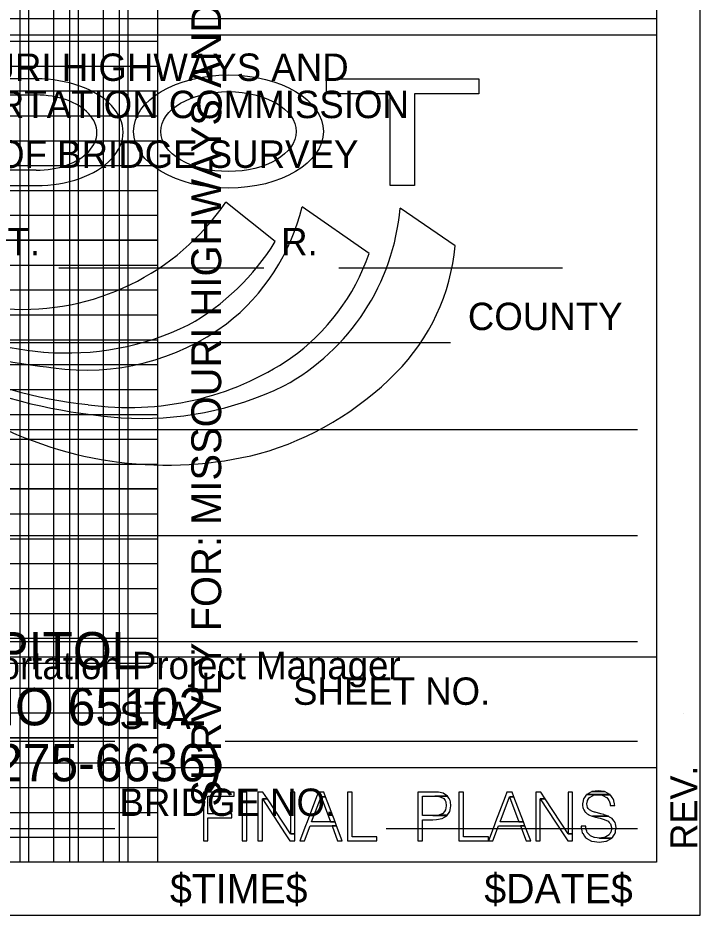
# Model space of a CAD drawing. Extents: x -0.2 to 31.4, y -0.2 to 20.6.
# Drawn here: x 28.681 to 31.425, y -0.212 to 3.393 of the extents above; entities that cross this region are included whole.
import ezdxf

# ---------------------------------------------------------------- set-up
doc = ezdxf.new("R2010")
doc.units = 0
for name, color, linetype in [('Border-Border', 7, 'Continuous'), ('Border-Bridge survey title block', 7, 'Continuous'), ('Border-Construction Final Plans Stamp', 7, 'Continuous'), ('Border-Cookie Cutter Template', 7, 'Continuous'), ('Border-Date stamp', 7, 'Continuous'), ('Border-English xsection major lines', 7, 'Continuous'), ('Border-English xsection minor lines', 7, 'Continuous'), ('Border-Full profile major grid lines', 7, 'Continuous'), ('Border-Geopak xsection major grid lines', 7, 'Continuous'), ('Border-Geopak xsection minor lines 1', 7, 'Continuous'), ('Border-Geopak xsection minor lines 2', 7, 'Continuous'), ('Border-Plan-profile major grid lines', 7, 'Continuous'), ('Border-Plotting block', 7, 'Continuous'), ('Border-Revision note', 7, 'Continuous'), ('Border-Time stamp', 7, 'Continuous'), ('Border-Title block - A-size Landscape Electronic Seal', 7, 'Continuous'), ('Border-Title block - Final Plans Consultant Manual Seal', 7, 'Continuous'), ('Border-Title block - Final Plans Electronic Seal', 7, 'Continuous'), ('Border-Title block - Location Survey Electronic Seal', 7, 'Continuous'), ('Border-Title block - Standard Plans Electronic Seal', 7, 'Continuous'), ('Border-Xsection shape', 7, 'Continuous')]:
    doc.layers.add(name, color=color, linetype=linetype)

msp = doc.modelspace()

# ---------------------------------------------------------------- linework, layer by layer
at = {"layer": 'Border-Border'}
for p, q in [((31.25, 20.375), (31.25, 0)), ((31.25, 0), (0, 0)), ((31.4249, -0.2125), (31.4249, -0.2125))]:
    msp.add_line(p, q, dxfattribs=at)
at = {"layer": 'Border-Bridge survey title block'}
for p, q in [((26.7664, 3.3906), (31.2499, 3.3906)), ((28.845, 2.389), (29.6704, 2.389)), ((29.9715, 2.389), (30.872, 2.389)), ((28.2689, 2.0882), (30.4216, 2.0882)), ((28.5253, 1.7386), (31.1728, 1.7386)), ((28.2056, 1.3126), (31.1728, 1.3126)), ((28.0914, 0.8866), (31.1728, 0.8866)), ((27.9544, 0.4866), (29.0704, 0.4866)), ((29.5148, 0.4866), (31.1728, 0.4866)), ((27.7414, 0.1354), (29.0704, 0.1354)), ((30.1618, 0.1354), (31.1728, 0.1354))]:
    msp.add_line(p, q, dxfattribs=at)
at = {"layer": 'Border-Construction Final Plans Stamp'}
msp.add_line((29.2421, 0.38), (31.2499, 0.38), dxfattribs=at)
for points in [[(29.4267, 0.1788), (29.4267, 0.0858), (29.4449, 0.0858), (29.4449, 0.1788), (29.541, 0.1788), (29.541, 0.1949), (29.4449, 0.1949), (29.4449, 0.2658), (29.5508, 0.2658), (29.5508, 0.2818), (29.4267, 0.2818), (29.4267, 0.2658), (29.4267, 0.1949)], [(29.583, 0.2818), (29.583, 0.0858), (29.6015, 0.0858), (29.6015, 0.2818)], [(29.6465, 0.1137), (29.6465, 0.0858), (29.6642, 0.0858), (29.6642, 0.1137), (29.6642, 0.254), (29.6846, 0.254), (29.6664, 0.2818), (29.6465, 0.2818), (29.6465, 0.254)], [(29.7564, 0.1137), (29.7748, 0.0858), (29.7947, 0.0858), (29.7947, 0.1137), (29.777, 0.1137), (29.6847, 0.254), (29.6642, 0.254)], [(29.777, 0.2818), (29.777, 0.1137), (29.7947, 0.1137), (29.7947, 0.2818)], [(29.8382, 0.1462), (29.8153, 0.0858), (29.834, 0.0858), (29.8565, 0.1462), (29.9627, 0.1462), (29.9567, 0.1619), (29.8623, 0.1619), (29.9004, 0.2629), (29.9183, 0.2629), (29.9112, 0.2818), (29.8897, 0.2818), (29.8825, 0.2629), (29.8442, 0.1619)], [(29.9004, 0.2629), (29.9385, 0.1619), (29.9567, 0.1619), (29.9184, 0.2629)], [(30.0063, 0.1018), (30.0063, 0.0858), (30.125, 0.0858), (30.125, 0.1018), (30.0248, 0.1018), (30.0248, 0.2818), (30.0063, 0.2818)], [(30.2897, 0.1709), (30.2897, 0.0858), (30.3078, 0.0858), (30.3078, 0.1709), (30.3495, 0.1709), (30.3641, 0.1714), (30.3869, 0.1754), (30.4062, 0.1862), (30.407, 0.1873), (30.3078, 0.1873), (30.3078, 0.1874), (30.3078, 0.189), (30.3078, 0.1961), (30.3078, 0.2043), (30.3078, 0.2103), (30.3078, 0.2269), (30.3078, 0.2271), (30.3078, 0.2432), (30.3078, 0.2473), (30.3078, 0.2557), (30.3078, 0.2632), (30.3078, 0.2649), (30.3078, 0.2654), (30.3078, 0.2658), (30.4084, 0.2658), (30.3921, 0.2768), (30.3724, 0.2812), (30.3583, 0.2818), (30.2897, 0.2818), (30.2897, 0.2812), (30.2897, 0.2768), (30.2897, 0.2658), (30.2897, 0.2654), (30.2897, 0.2649), (30.2897, 0.2632), (30.2897, 0.2557), (30.2897, 0.2473), (30.2897, 0.2432), (30.2897, 0.2271), (30.2897, 0.2269), (30.2897, 0.2103), (30.2897, 0.2043), (30.2897, 0.1961), (30.2897, 0.189), (30.2897, 0.1874), (30.2897, 0.1873), (30.2897, 0.1862), (30.2897, 0.1754), (30.2897, 0.1714)], [(30.3574, 0.2658), (30.3644, 0.2654), (30.4089, 0.2654), (30.4084, 0.2658)], [(30.3907, 0.1961), (30.3747, 0.189), (30.4081, 0.189), (30.413, 0.1961), (30.4186, 0.2043), (30.4197, 0.2103), (30.4196, 0.2103), (30.4226, 0.2269), (30.4226, 0.2271), (30.4204, 0.2432), (30.4199, 0.2473), (30.415, 0.2557), (30.4106, 0.2632), (30.4096, 0.2649), (30.4089, 0.2654), (30.3644, 0.2654), (30.3678, 0.2649), (30.3794, 0.2632), (30.3936, 0.2557), (30.3991, 0.2473), (30.4017, 0.2432), (30.4041, 0.2271), (30.4041, 0.2269), (30.4012, 0.2103), (30.3968, 0.2043)], [(30.4545, 0.1018), (30.4545, 0.0858), (30.5732, 0.0858), (30.5732, 0.1018), (30.473, 0.1018), (30.473, 0.2818), (30.4545, 0.2818)], [(30.5961, 0.1462), (30.5732, 0.0858), (30.5919, 0.0858), (30.6144, 0.1462), (30.7206, 0.1462), (30.7146, 0.1619), (30.6202, 0.1619), (30.6583, 0.2629), (30.6762, 0.2629), (30.6691, 0.2818), (30.6476, 0.2818), (30.6404, 0.2629), (30.6021, 0.1619)], [(30.6583, 0.2629), (30.6964, 0.1619), (30.7146, 0.1619), (30.6763, 0.2629)], [(30.7642, 0.1137), (30.7642, 0.0858), (30.7819, 0.0858), (30.7819, 0.1137), (30.7819, 0.254), (30.8024, 0.254), (30.7841, 0.2818), (30.7642, 0.2818), (30.7642, 0.254)], [(30.8742, 0.1137), (30.8925, 0.0858), (30.9124, 0.0858), (30.9124, 0.1137), (30.8947, 0.1137), (30.8024, 0.254), (30.7819, 0.254)], [(30.8947, 0.2818), (30.8947, 0.1137), (30.9124, 0.1137), (30.9124, 0.2818)], [(30.9904, 0.1853), (30.9927, 0.1844), (31.0561, 0.1844), (31.0546, 0.1853), (31.0395, 0.1906), (31.0394, 0.1906), (31.0378, 0.1912), (31.0257, 0.1946), (31.0029, 0.2004), (31.0002, 0.2012), (30.9921, 0.2036), (30.9798, 0.2103), (30.9753, 0.2161), (30.9721, 0.2203), (30.9707, 0.2272), (30.9695, 0.2337), (30.9695, 0.2339), (30.9695, 0.2344), (30.9696, 0.2349), (30.9717, 0.2471), (30.9719, 0.2486), (30.976, 0.2543), (30.9765, 0.2549), (30.9765, 0.2549), (30.9801, 0.2599), (30.9805, 0.2605), (30.9953, 0.2685), (30.9959, 0.2689), (31.0147, 0.2711), (31.0635, 0.2711), (31.0628, 0.2721), (30.9684, 0.2721), (30.9677, 0.2711), (30.966, 0.2689), (30.9658, 0.2685), (30.96, 0.2605), (30.9596, 0.2599), (30.9559, 0.2549), (30.9555, 0.2543), (30.9544, 0.2486), (30.9541, 0.2471), (30.9517, 0.2349), (30.9516, 0.2344), (30.9517, 0.2339), (30.9517, 0.2337), (30.9526, 0.2272), (30.9536, 0.2203), (30.9542, 0.2161), (30.9575, 0.2103), (30.9615, 0.2036), (30.9629, 0.2012), (30.964, 0.2004), (30.9714, 0.1946), (30.9758, 0.1912), (30.9765, 0.1906)], [(30.9693, 0.2726), (30.9684, 0.2721), (31.0628, 0.2721), (31.0624, 0.2726), (31.0425, 0.2832), (31.0399, 0.2836), (30.9893, 0.2836), (30.9886, 0.2832)], [(31.0156, 0.2872), (30.9893, 0.2836), (31.0399, 0.2836)], [(31.063, 0.2337), (31.0634, 0.2272), (31.0815, 0.2272), (31.0811, 0.2337), (31.0811, 0.2339), (31.0811, 0.2344), (31.0811, 0.2349), (31.0778, 0.2471), (31.0778, 0.2471), (31.0774, 0.2486), (31.0759, 0.2543), (31.0757, 0.2549), (31.0719, 0.2599), (31.0715, 0.2605), (31.0654, 0.2685), (31.0652, 0.2689), (31.0652, 0.2689), (31.0635, 0.2711), (31.0147, 0.2711), (31.0313, 0.2689), (31.0336, 0.2685), (31.0489, 0.2605), (31.05, 0.2599), (31.0537, 0.2549), (31.0541, 0.2543), (31.0582, 0.2486), (31.0593, 0.2471), (31.0627, 0.2349), (31.0628, 0.2344), (31.0629, 0.2339)], [(30.3573, 0.1874), (30.3498, 0.1873), (30.407, 0.1873), (30.407, 0.1874)], [(30.3746, 0.189), (30.3574, 0.1874), (30.407, 0.1874), (30.4081, 0.189)], [(31.0224, 0.0968), (31.02, 0.0965), (31.0694, 0.0965), (31.0699, 0.0968), (31.0712, 0.0976), (31.0721, 0.0988), (31.0725, 0.0994), (31.0771, 0.1061), (31.0795, 0.1096), (31.0835, 0.1154), (31.0839, 0.1183), (31.0839, 0.1183), (31.0841, 0.1197), (31.0848, 0.1245), (31.0863, 0.1343), (31.0868, 0.1377), (31.0871, 0.1392), (31.0842, 0.1536), (31.0829, 0.1598), (31.0791, 0.1646), (31.0734, 0.1721), (31.0708, 0.1754), (31.0689, 0.1766), (31.0689, 0.1766), (31.0611, 0.1813), (31.0561, 0.1844), (30.9927, 0.1844), (31.0046, 0.1813), (31.0232, 0.1766), (31.0272, 0.1754), (31.0392, 0.1721), (31.0552, 0.1646), (31.0596, 0.1598), (31.0652, 0.1536), (31.0688, 0.1392), (31.0687, 0.1377), (31.0684, 0.1343), (31.0677, 0.1245), (31.0649, 0.1197), (31.0641, 0.1183), (31.0624, 0.1154), (31.0591, 0.1096), (31.0531, 0.1061), (31.0416, 0.0994), (31.0374, 0.0988), (31.028, 0.0976)], [(29.9444, 0.1462), (29.9668, 0.0858), (29.9856, 0.0858), (29.9627, 0.1462)], [(30.7022, 0.1462), (30.7247, 0.0858), (30.7435, 0.0858), (30.7206, 0.1462)], [(30.9897, 0.0843), (31.0197, 0.0805), (31.0452, 0.0843), (31.049, 0.0849), (31.0694, 0.0965), (31.02, 0.0965), (31.0174, 0.0968), (31.011, 0.0976), (31.0003, 0.0988), (30.999, 0.0994), (30.9835, 0.1061), (30.9803, 0.1096), (30.9748, 0.1154), (30.9748, 0.1154), (30.9721, 0.1183), (30.9709, 0.1197), (30.9692, 0.1245), (30.9658, 0.1343), (30.9654, 0.1377), (30.9653, 0.1392), (30.9648, 0.1452), (30.9468, 0.1452), (30.9469, 0.1392), (30.947, 0.1377), (30.9477, 0.1343), (30.9496, 0.1245), (30.9505, 0.1197), (30.9508, 0.1183), (30.9528, 0.1154), (30.9569, 0.1096), (30.9593, 0.1061), (30.964, 0.0994), (30.9645, 0.0988), (30.9653, 0.0976), (30.9659, 0.0968), (30.9665, 0.0965), (30.9886, 0.0849)]]:
    msp.add_lwpolyline(points, close=True, dxfattribs=at)
at = {"layer": 'Border-Cookie Cutter Template'}
for p, q in [((29.2421, 20.375), (29.2421, 0)), ((31.2499, 20.375), (31.2499, 0)), ((31.2499, 0), (0, 0))]:
    msp.add_line(p, q, dxfattribs=at)
at = {"layer": 'Border-English xsection major lines'}
for p, q in [((0, 3), (29.2421, 3)), ((0, 2), (29.2421, 2)), ((0, 1), (29.2421, 1))]:
    msp.add_line(p, q, dxfattribs=at)
at = {"layer": 'Border-English xsection minor lines'}
for p, q in [((28.6899, 0), (28.6899, 20.375)), ((28.8899, 0), (28.8899, 20.375)), ((29.0899, 0), (29.0899, 20.375)), ((0, 3.2), (29.2421, 3.2)), ((0, 2.8), (29.2421, 2.8)), ((0, 2.6), (29.2421, 2.6)), ((0, 2.4), (29.2421, 2.4)), ((0, 2.2), (29.2421, 2.2)), ((0, 1.8), (29.2421, 1.8)), ((0, 1.6), (29.2421, 1.6)), ((0, 1.4), (29.2421, 1.4)), ((0, 1.2), (29.2421, 1.2)), ((0, 0.8), (29.2421, 0.8)), ((0, 0.6), (29.2421, 0.6)), ((0, 0.4), (29.2421, 0.4)), ((0, 0.2), (29.2421, 0.2))]:
    msp.add_line(p, q, dxfattribs=at)
at = {"layer": 'Border-Full profile major grid lines'}
for p, q in [((29.2421, 2.5), (0, 2.5)), ((29.2421, 1.5), (0, 1.5)), ((29.2421, 0.5), (0, 0.5))]:
    msp.add_line(p, q, dxfattribs=at)
at = {"layer": 'Border-Geopak xsection major grid lines'}
for p, q in [((0, 3), (29.2421, 3)), ((0, 2), (29.2421, 2)), ((0, 1), (29.2421, 1))]:
    msp.add_line(p, q, dxfattribs=at)
at = {"layer": 'Border-Geopak xsection minor lines 1'}
for p, q in [((28.7249, 0), (28.7249, 20.375)), ((28.9249, 0), (28.9249, 20.375)), ((29.1249, 0), (29.1249, 20.375)), ((0, 3.3), (29.2421, 3.3)), ((0, 3.1), (29.2421, 3.1)), ((0, 2.9), (29.2421, 2.9)), ((0, 2.7), (29.2421, 2.7)), ((0, 2.5), (29.2421, 2.5)), ((0, 2.3), (29.2421, 2.3)), ((0, 2.1), (29.2421, 2.1)), ((0, 1.9), (29.2421, 1.9)), ((0, 1.7), (29.2421, 1.7)), ((0, 1.5), (29.2421, 1.5)), ((0, 1.3), (29.2421, 1.3)), ((0, 1.1), (29.2421, 1.1)), ((0, 0.9), (29.2421, 0.9)), ((0, 0.7), (29.2421, 0.7)), ((0, 0.5), (29.2421, 0.5)), ((0, 0.3), (29.2421, 0.3)), ((0, 0.1), (29.2421, 0.1))]:
    msp.add_line(p, q, dxfattribs=at)
at = {"layer": 'Border-Geopak xsection minor lines 2'}
for p, q in [((28.8249, 0), (28.8249, 20.375)), ((29.0249, 0), (29.0249, 20.375)), ((0, 3.2), (29.2421, 3.2)), ((0, 2.8), (29.2421, 2.8)), ((0, 2.6), (29.2421, 2.6)), ((0, 2.4), (29.2421, 2.4)), ((0, 2.2), (29.2421, 2.2)), ((0, 1.8), (29.2421, 1.8)), ((0, 1.6), (29.2421, 1.6)), ((0, 1.4), (29.2421, 1.4)), ((0, 1.2), (29.2421, 1.2)), ((0, 0.8), (29.2421, 0.8)), ((0, 0.6), (29.2421, 0.6)), ((0, 0.4), (29.2421, 0.4)), ((0, 0.2), (29.2421, 0.2))]:
    msp.add_line(p, q, dxfattribs=at)
at = {"layer": 'Border-Plan-profile major grid lines'}
for p, q in [((29.2421, 2.5), (0, 2.5)), ((29.2421, 1.5), (0, 1.5)), ((29.2421, 0.5), (0, 0.5))]:
    msp.add_line(p, q, dxfattribs=at)
at = {"layer": 'Border-Plotting block'}
msp.add_lwpolyline([(-0.175, -0.2125), (31.4249, -0.2125), (31.4249, 20.5875), (-0.175, 20.5875)], close=True, dxfattribs=at)
at = {"layer": 'Border-Revision note'}
msp.add_line((31.3597, 0.5967), (31.3597, 0.5967), dxfattribs=at)
at = {"layer": 'Border-Title block - A-size Landscape Electronic Seal'}
for p, q in [((28.7545, 3.1483), (28.4475, 3.1483)), ((28.5533, 3.0837), (28.7545, 3.0837)), ((28.7545, 2.781), (28.5533, 2.781)), ((28.4475, 2.7194), (28.7545, 2.7194)), ((29.7157, 2.4943), (29.5176, 2.6534)), ((30.0933, 2.4462), (29.8242, 2.6347)), ((30.4395, 2.4776), (30.2183, 2.6283))]:
    msp.add_line(p, q, dxfattribs=at)
msp.add_lwpolyline([(29.9217, 3.1485), (30.5352, 3.1485), (30.5352, 3.0888), (30.2761, 3.0888), (30.2761, 2.7194), (30.1789, 2.7194), (30.1789, 3.0888), (29.9217, 3.0888)], close=True, dxfattribs=at)
for centre, radius, start, end in [((28.7015, 3.2095), 0.9875, 266.1033, 325.7272), ((28.7015, 3.2095), 0.9875, 325.7274, 325.7276), ((28.9983, 2.8346), 0.8497, 307.8205, 346.3964), ((29.3188, 2.7072), 0.903, 298.5725, 354.9889), ((28.8971, 2.9975), 0.9608, 299.2666, 328.4191), ((29.6134, 2.5513), 0.8294, 315.1693, 354.902), ((29.2754, 2.7303), 0.8658, 305.4806, 340.8474), ((29.0337, 4.1035), 2.1265, 240.8019, 264.3058), ((28.9712, 3.9787), 1.9374, 248.3366, 264.4662), ((28.8777, 3.1629), 1.1164, 265.2048, 295.9837), ((28.9566, 2.9249), 0.9469, 261.8718, 306.464), ((29.1275, 2.9948), 1.1675, 261.9272, 303.854), ((29.1645, 3.6951), 1.867, 244.3097, 263.8237), ((29.311, 2.8469), 1.2523, 285.8221, 315.3322), ((29.2595, 4.0405), 2.2598, 249.2778, 265.8465), ((29.1813, 3.0917), 1.3079, 266.2526, 295.8037), ((29.2792, 3.1295), 1.5336, 241.4589, 284.0852)]:
    msp.add_arc(centre, radius, start, end, dxfattribs=at)
for centre, major_axis, ratio in [((28.7545, 2.9339), (-0.3494, 0), 0.614143), ((28.7545, 2.9324), (-0.2438, 0), 0.62091)]:
    msp.add_ellipse(centre, major_axis=major_axis, ratio=ratio, start_param=1.570796, end_param=4.712389, dxfattribs=at)
for centre, major_axis, ratio in [((29.5278, 2.9367), (0.382, 0), 0.595517), ((29.5277, 2.9367), (-0.2725, 0), 0.589579)]:
    msp.add_ellipse(centre, major_axis=major_axis, ratio=ratio, dxfattribs=at)
at = {"layer": 'Border-Title block - Final Plans Consultant Manual Seal'}
msp.add_line((29.2421, 20.375), (29.2421, 0), dxfattribs=at)
at = {"layer": 'Border-Title block - Final Plans Electronic Seal'}
msp.add_line((29.2421, 20.375), (29.2421, 0), dxfattribs=at)
at = {"layer": 'Border-Title block - Location Survey Electronic Seal'}
msp.add_line((29.2421, 20.375), (29.2421, 0), dxfattribs=at)
at = {"layer": 'Border-Title block - Standard Plans Electronic Seal'}
for p, q in [((23.2499, 3.325), (31.25, 3.325)), ((23.2499, 0.825), (31.25, 0.825)), ((29.2421, 0.825), (29.2421, 0))]:
    msp.add_line(p, q, dxfattribs=at)
at = {"layer": 'Border-Xsection shape'}
msp.add_lwpolyline([(29.2421, 0), (0, 0), (0, 20.375), (29.2421, 20.375)], close=True, dxfattribs=at)

# ---------------------------------------------------------------- texts
at = {"layer": 'Border-Bridge survey title block'}
for s, height, p in [('MISSOURI HIGHWAYS AND', 0.110166, (28.0878, 3.1402)), ('TRANSPORTATION COMMISSION', 0.110192, (27.8878, 2.9906)), ('REPORT OF BRIDGE SURVEY', 0.110192, (27.9381, 2.7906)), ('T.', 0.11019, (28.6389, 2.4393)), ('R.', 0.11019, (29.7397, 2.4393)), ('COUNTY', 0.11019, (30.4909, 2.1386)), ('Transportation Project Manager', 0.110166, (28.1488, 0.7355)), ('STA.', 0.11019, (29.0893, 0.5354)), ('BRIDGE NO.', 0.11019, (29.0893, 0.1858))]:
    msp.add_text(s, height=height, dxfattribs=at).set_placement(p)
at = {"layer": 'Border-Date stamp'}
msp.add_text('$DATE$', height=0.11811, dxfattribs=at).set_placement((30.5571, -0.1653))
at = {"layer": 'Border-Revision note'}
msp.add_text('REV.', height=0.10827, rotation=90, dxfattribs=at).set_placement((31.4138, 0.0505))
at = {"layer": 'Border-Time stamp'}
msp.add_text('$TIME$', height=0.11811, dxfattribs=at).set_placement((29.2927, -0.1653))
at = {"layer": 'Border-Title block - A-size Landscape Electronic Seal'}
for s, p in [('105 WEST CAPITOL', (27.2857, 0.775)), ('JEFFERSON CITY, MO 65102', (26.6857, 0.55)), ('1-888-ASK-MODOT (1-888-275-6636)', (26.0919, 0.325))]:
    msp.add_text(s, height=0.15, dxfattribs=at).set_placement(p)
at = {"layer": 'Border-Title block - Location Survey Electronic Seal'}
msp.add_text('SURVEY FOR: MISSOURI HIGHWAYS AND TRANSPORTATION COMMISSION', height=0.12, rotation=90, dxfattribs=at).set_placement((29.4984, 0.2231))
at = {"layer": 'Border-Title block - Standard Plans Electronic Seal'}
msp.add_text('SHEET NO.', height=0.11, dxfattribs=at).set_placement((29.7878, 0.6325))

doc.saveas('drawing.dxf')
